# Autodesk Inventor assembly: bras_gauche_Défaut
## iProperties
Shininess: 64.0
Length Units: 11269
Angle Units: 11279
Time Units: 11290
Mass Units: 11283
Length Display Precision: 3
Angle Display Precision: 2
Compacted: True
Created: 2006-01
Part Number: bras_gauche_Défaut
Document SubType Name: Assembly
Designer: riri
Density: 0.0
Volumn: 0.0
Area: 0.0
PropertySet Name: Model Information
Control State: 0
Master: False
Checked Out: False
Author: riri
